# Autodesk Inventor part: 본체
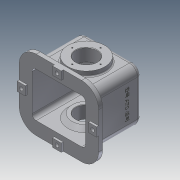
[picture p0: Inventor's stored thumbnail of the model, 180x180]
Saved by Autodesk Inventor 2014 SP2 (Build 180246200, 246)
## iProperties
Created: 2014-11
Part Number: 본체
Material: 알루미늄 6061
Document SubType Name: Modeling
Designer: 201-12
Density: 2.71 g/cm^3
Appearance: 알루미늄 - 평지
Mass: 2962.33 g
Surface Area: 2124.66 cm^2
Volume: 1093.11 cm^3
Author: 201-12
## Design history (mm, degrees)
sketch "스케치2"
  geometry: L1 (-98, 87)-(98, 87); L2 (98, 87)-(98, -87); L3 (98, -87)-(-98, -87); L4 (-98, -87)-(-98, 87); L5 (-98, 87)-(98, -87); L6 (98, 87)-(-98, -87); 1 further point
  constraints: 12 end point, 2 midpoint, 2 parallel, 1 horizontal, 1 perpendicular
  dimensions: "d2" = 196 distance of L2.end L3.end; "d3" = 174 distance of L1.end L2.end
extrude "돌출1" new body sketch "스케치2" distance "d4" = 10; taper "d5" = 0 deg
sketch "스케치3"
  geometry: L1 (-76, 65)-(76, 65); L2 (76, 65)-(76, -65); L3 (76, -65)-(-76, -65); L4 (-76, -65)-(-76, 65); L5 (-76, 65)-(76, -65); L6 (76, 65)-(-76, -65); 1 further point
  constraints: 12 end point, 2 midpoint, 2 parallel, 1 horizontal, 1 perpendicular
  dimensions: "d6" = 152 distance of L2.end L3.end; "d7" = 130 distance of L1.end L2.end
extrude "돌출2" join sketch "스케치3" distance "d8" = 118; taper "d9" = 0 deg
node "작업 평면2"
node "작업 평면3"
sketch "스케치5"
  geometry: L1 (76, -65)-(76, 65) reference; 1 further point
node "작업 평면5"
  node "작업 평면4"
sketch "스케치15"
  geometry: L1 (-98, -10)-(98, -10) reference; L2 (0, 58)-(17.88, 142.121); L3 (0, 58)-(54.453, 58); L4 (17.88, 142.121)-(-12.442, 148.566); L5 (-12.442, 148.566)-(-19.259, 116.497); L6 (-19.259, 116.497)-(11.064, 110.052); L7 (11.064, 110.052)-(17.88, 142.121); 1 further point
  constraints: 12 end point, 2 parallel, 2 perpendicular, 1 collinear, 1 vertical alignment
  dimensions: "d95" = 68 distance from line of L1 L2.start; "d96" = 78 deg angle of L3 L2; "d97" = 86 distance of L2.start L2.end; "d98" = 31 distance of L2.end L4.end; "d99" = 32.78514 distance of L4.end L5.end
revolve "회전2" sketch "스케치15" stored, may be unused: angle "d100" = 90 deg
sketch "스케치4"
  geometry: L1 (-66, 55)-(66, 55); L2 (66, 55)-(66, -55); L3 (66, -55)-(-66, -55); L4 (-66, -55)-(-66, 55); L5 (-66, 55)-(66, -55); L6 (66, 55)-(-66, -55); 1 further point
  constraints: 12 end point, 2 midpoint, 2 parallel, 1 horizontal, 1 perpendicular
  dimensions: "d10" = 132 distance of L2.end L3.end; "d11" = 110 distance of L1.end L2.end
extrude "돌출3" cut sketch "스케치4" distance "d12" = 118; taper "d13" = 0 deg
sketch "스케치7"
  geometry: L1 (174, -10)-(-22, -10) reference; L2 (174, 0)-(-22, 0) reference; C1 r 45.5 at (76, 58); 2 further points
  constraints: 1 centre point, 1 midpoint, 1 vertical alignment
  dimensions: "d22" = 91 diameter of C1; "d23" = 68 distance from line of C1.centre L1
extrude "돌출5" join sketch "스케치7" distance "d24" = 12; taper "d25" = 0 deg
sketch "스케치8"
  geometry: C1 r 45.5 at (0, 0) reference; C2 r 26 at (0, 0); 1 further point
  constraints: 1 centre point, 1 coincident
  dimensions: "d26" = 52 diameter of C2
extrude "돌출6" cut sketch "스케치8" stored distance "d27" = 12; taper "d28" = 0 deg
sketch "스케치9"
  geometry: L1 (58, 0)-(58, -74.77); L2 (84, -77)-(84, -55) reference; L3 (32, -77)-(32, -55) reference; L4 (84, -55)-(84, -45); L5 (84, -45)-(93.5, -45); L6 (93.5, -45)-(103.5, -55); L7 (103.5, -55)-(84, -55); 1 further point
  constraints: 10 end point, 3 parallel, 1 horizontal alignment, 1 perpendicular, 1 vertical
  dimensions: "d29" = 26 horizontal distance of L2.start L1.end; "d30" = 74.76996 distance of L1.start L1.end; "d31" = 71 diameter of L5.end L1; "d32" = 91 diameter of L6.end L1; "d33" = 10 distance of L2.end L4.end
revolve "회전1" sketch "스케치9" stored, may be unused: angle "d34" = 90 deg
sketch "스케치11" dims "d35" = 70
  geometry: C1 r 26 at (0, 0) reference; C2 r 45.5 at (0, 0) reference; 6 further points
  constraints: 3 vertical alignment, 1 coincident, 7 other
  dimensions: "d38" = 360 deg dimension on point (0, 0) point (0, 35) (derived)
hole "구멍1" sketch "스케치11" at (0, 35), (-35, 0), (0, -35), (35, 0) diameter "d40" = 3.242; stored, may be unused: countersink angle "d44" = 90 deg, drill point angle "d46" = 118 deg; dims "d41" = 13, "d42" = 4, "d43" = 2, "d45" = 16
sketch "스케치12"
  geometry: L1 (98, 87)-(-98, 87) reference; L2 (-98, 87)-(-98, -87) reference; L3 (-98, -87)-(98, -87) reference; L4 (98, -87)-(98, 87) reference; L5 (-11, 87)-(11, 87); L6 (11, 87)-(11, 67); L7 (11, 67)-(-11, 67); L8 (-11, 67)-(-11, 87); L9 (-98, 11)-(-78, 11); L10 (-78, 11)-(-78, -11); L11 (-78, -11)-(-98, -11); L12 (-98, -11)-(-98, 11); L13 (-11, -67)-(11, -67); L14 (11, -67)-(11, -87); L15 (11, -87)-(-11, -87); L16 (-11, -87)-(-11, -67); L17 (78, 11)-(98, 11); L18 (98, 11)-(98, -11); L19 (98, -11)-(78, -11); L20 (78, -11)-(78, 11); 1 further point
  constraints: 32 end point, 8 parallel, 4 horizontal, 4 perpendicular, 4 point on line
  dimensions: "d47" = 22 distance of L5.start L5.end; "d48" = 20 distance of L5.end L6.end; "d49" = 11 distance from line of L6 point (0, 0); "d50" = 22 distance of L17.end L18.end; "d51" = 22 distance between parallel lines of L16 L14; "d52" = 22 distance between parallel lines of L11 L9; "d53" = 11 distance from line of point (0, 0) L11; "d54" = 20 distance of L10.end L11.end; "d55" = 20 distance of L15.end L13.start; "d56" = 20 distance of L18.end L19.end; "d57" = 11 distance from line of point (0, 0) L19; "d58" = 11 distance from line of point (0, 0) L16
extrude "돌출7" join sketch "스케치12" distance "d59" = 5; taper "d60" = 0 deg
sketch "스케치13"
  geometry: L1 (98, -87)-(-98, -87) reference; L2 (98, 87)-(98, -87) reference; L3 (-98, 87)-(98, 87) reference; L4 (-98, -87)-(-98, 87) reference; 5 further points
  constraints: 2 horizontal alignment, 2 vertical alignment
  dimensions: "d61" = 10 distance from line of L3 point (0, 77); "d62" = 10 distance from line of L2 point (88, 0); "d63" = 10 distance from line of L1 point (0, -77); "d64" = 10 distance from line of L4 point (-88, 0)
hole "구멍2" sketch "스케치13" at (88, 0), (0, 77), (-88, 0), (0, -77) diameter "d65" = 9; stored, may be unused: countersink angle "d69" = 90 deg, drill point angle "d71" = 118 deg; dims "d66" = 13, "d67" = 14, "d68" = 8.6, "d70" = 16
fillet "모깎기1" dims "d72" = 42
fillet "모깎기2" dims "d73" = 20
fillet "모깎기4" dims "d75" = 10
fillet "모깎기5" dims "d76" = 3
hole "구멍3" diameter "d79" = 30; stored, may be unused: countersink angle "d83" = 90 deg, drill point angle "d85" = 118 deg; dims "d80" = 13, "d81" = 42, "d82" = 25, "d84" = 16, "d101" = 10, "d102" = 10
fillet "모깎기6" dims "d86" = 0.3
node "작업 평면7"
sketch "스케치14"
  geometry: L1 (34, -118)-(0, -118) reference; 2 further points
  constraints: 1 vertical alignment, 1 other
  dimensions: "d88" = 92 distance from line of L1 point (45, -26)
feature "엠보싱1" sketch "스케치14" dims "d2" = 196, "d3" = 174, "d10" = 132, "d11" = 110, "d89" = 1, "d90" = 0
chamfer "모따기1" distance "d91" = 1; stored, may be unused: second distance "d92" = 2, angle "d93" = 45 deg
fillet "모깎기7" dims "d103" = 3
node "솔리드1"
mirror "대칭2"
other parameters: "d15" = -68, "d16" = 12 deg, "d17" = -12 deg, "d18" = -86, "d87" = 72
